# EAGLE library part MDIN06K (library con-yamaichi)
YAMAICHI CONNECTOR
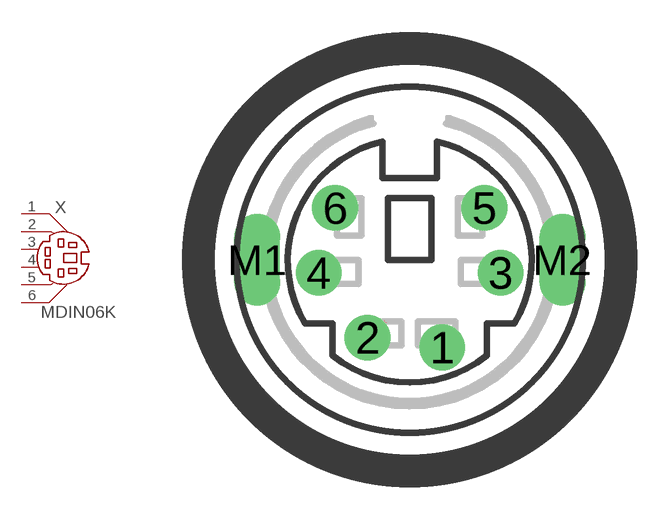
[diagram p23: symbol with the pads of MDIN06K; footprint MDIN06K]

Designator prefix X

## MDIN06K (OC_FARNELL: unknown; OC_NEWARK: unknown)  [MDIN06K]
1  1  pas
2  2  pas
3  3  pas
4  4  pas
5  5  pas
6  6  pas

## Footprint MDIN06K (pad centres in mm)
Mini Din YAMAICHI CONNECTOR
drill 0.9 round: 1 1,-2.7; 2 -1.3,-2.4; 3 2.8,-0.4; 4 -2.8,-0.4; 5 2.3,1.6; 6 -2.3,1.6
drill 0.9 long: M1 -4.7,0; M2 4.7,0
